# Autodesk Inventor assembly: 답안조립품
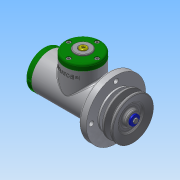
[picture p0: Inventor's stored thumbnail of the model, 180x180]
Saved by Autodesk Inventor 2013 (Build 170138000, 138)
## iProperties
Created: 2016-08
Part Number: 답안조립품
Document SubType Name: Assembly
Designer: Administrator
Author: Administrator
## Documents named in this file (25)
- C:\Users\Administrator\Desktop\460807V1013\답안조립품.iam
- C:\Users\Administrator\Desktop\460807V1013\1-본체.ipt
- C:\Users\Administrator\Desktop\460807V1013\편심축.ipt
- C:\Users\Administrator\Desktop\460807V1013\베어링 15 x 35 x 11.ipt
- C:\Users\Administrator\Desktop\460807V1013\부시1.ipt
- C:\Users\Administrator\Desktop\460807V1013\멈춤링 35x1.6.ipt
- C:\Users\Administrator\Desktop\460807V1013\멈춤링 15 x 1.ipt
- C:\Users\Administrator\Desktop\460807V1013\부시2.ipt
- C:\Users\Administrator\Desktop\460807V1013\와셔 10x21.ipt
- C:\Users\Administrator\Desktop\460807V1013\너트 M10.ipt
- C:\Users\Administrator\Desktop\460807V1013\사이드 커버.ipt
- 사이드 커버.ipt
- C:\Users\Administrator\Desktop\460807V1013\링크.ipt
- C:\Users\Administrator\Desktop\460807V1013\슬라이더.ipt
- C:\Users\Administrator\Desktop\460807V1013\클래스터 핀 6 x 24.ipt
- C:\Users\Administrator\Desktop\460807V1013\분할핀 1.6 x 12.ipt
- C:\Users\Administrator\Desktop\460807V1013\탑 커버.ipt
- 탑 커버.ipt
- C:\Users\Administrator\Desktop\460807V1013\탑 부시.ipt
- C:\Users\Administrator\Desktop\460807V1013\볼트 M4 x 12.ipt
- C:\Users\Administrator\Desktop\460807V1013\오일 실 15 25 7.ipt
- C:\Users\Administrator\Desktop\460807V1013\키 4 x 4 x 18.ipt
- C:\Users\Administrator\Desktop\460807V1013\V-벨트풀리.ipt
- C:\Users\Administrator\Desktop\460807V1013\와셔 4x16.ipt
- C:\Users\Administrator\Desktop\460807V1013\볼트 M4 x 10.ipt
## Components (7 placed, 4 different names)
1. 1-본체:1
2. V-벨트풀리:1
3. ISO 4017 M4 x 10:1
4. ISO 4762 M4 x 12:1
5. ISO 4762 M4 x 12:2
6. ISO 4762 M4 x 12:3
7. ISO 4762 M4 x 12:4
